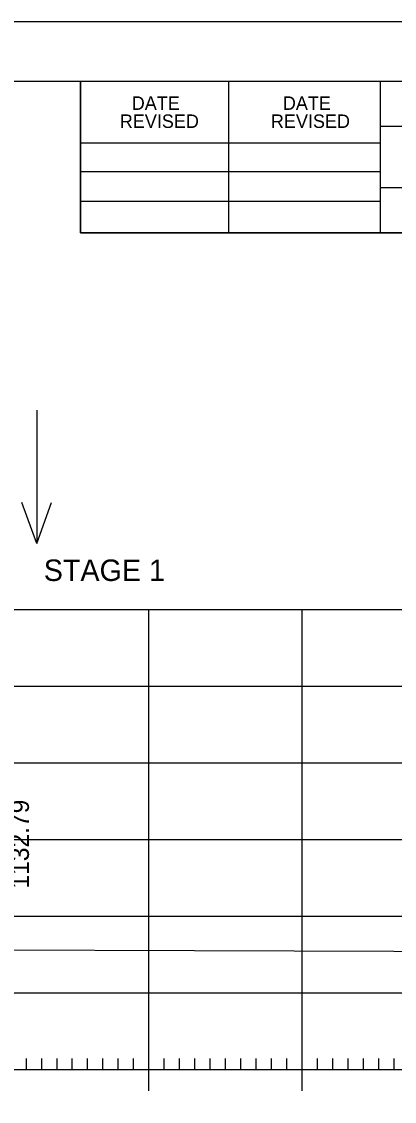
# Model space of a CAD drawing. Extents: x 1322838 to 1324533, y 339903 to 351025.
# Drawn here: x 1323795.4 to 1323819.7, y 342179.4 to 342249.8 of the extents above; entities that cross this region are included whole.
import ezdxf

# ---------------------------------------------------------------- set-up
doc = ezdxf.new("R2010")
doc.units = 0
for name, color, linetype in [('R_Axis', 7, 'Continuous'), ('R_Axis Annot', 7, 'Continuous'), ('R_Border', 7, 'Continuous'), ('R_Exist Surface', 7, 'Continuous'), ('R_Fin Surface Annot', 7, 'Continuous'), ('R_Grid', 7, 'Continuous'), ('R_No Plot', 7, 'Continuous'), ('R_Water Annot', 7, 'Continuous')]:
    doc.layers.add(name, color=color, linetype=linetype)

msp = doc.modelspace()

# ---------------------------------------------------------------- linework, layer by layer
at = {"layer": 'R_Axis'}
for p, q in [((1323803.715, 342180.082), (1323803.715, 342182.882)), ((1323813.715, 342180.082), (1323813.715, 342182.882)), ((1323795.715, 342181.482), (1323795.715, 342182.182)), ((1323796.715, 342181.482), (1323796.715, 342182.182)), ((1323797.715, 342181.482), (1323797.715, 342182.182)), ((1323798.715, 342181.482), (1323798.715, 342182.182)), ((1323799.715, 342181.482), (1323799.715, 342182.182)), ((1323800.715, 342181.482), (1323800.715, 342182.182)), ((1323801.715, 342181.482), (1323801.715, 342182.182)), ((1323802.715, 342181.482), (1323802.715, 342182.182)), ((1323804.715, 342181.482), (1323804.715, 342182.182)), ((1323805.715, 342181.482), (1323805.715, 342182.182)), ((1323806.715, 342181.482), (1323806.715, 342182.182)), ((1323807.715, 342181.482), (1323807.715, 342182.182)), ((1323808.715, 342181.482), (1323808.715, 342182.182)), ((1323809.715, 342181.482), (1323809.715, 342182.182)), ((1323810.715, 342181.482), (1323810.715, 342182.182)), ((1323811.715, 342181.482), (1323811.715, 342182.182)), ((1323812.715, 342181.482), (1323812.715, 342182.182)), ((1323814.715, 342181.482), (1323814.715, 342182.182)), ((1323815.715, 342181.482), (1323815.715, 342182.182)), ((1323816.715, 342181.482), (1323816.715, 342182.182)), ((1323817.715, 342181.482), (1323817.715, 342182.182)), ((1323818.715, 342181.482), (1323818.715, 342182.182)), ((1323819.715, 342181.482), (1323819.715, 342182.182)), ((1323563.715, 342181.482), (1323843.715, 342181.482))]:
    msp.add_line(p, q, dxfattribs=at)
at = {"layer": 'R_Border'}
for p, q in [((1323545.715, 342245.942), (1323861.895, 342245.942)), ((1323799.255, 342236.062), (1323799.255, 342245.942)), ((1323808.935, 342236.062), (1323808.935, 342245.942)), ((1323818.795, 342245.942), (1323818.795, 342236.062)), ((1323861.895, 342243.002), (1323818.795, 342243.002)), ((1323799.255, 342241.922), (1323818.795, 342241.922)), ((1323799.255, 342240.062), (1323818.795, 342240.062)), ((1323861.895, 342239.002), (1323818.795, 342239.002)), ((1323799.255, 342238.122), (1323818.795, 342238.122)), ((1323861.895, 342236.062), (1323799.255, 342236.062))]:
    msp.add_line(p, q, dxfattribs=at)
at = {"layer": 'R_Exist Surface'}
msp.add_lwpolyline([(1323780.633, 342189.331), (1323819.688, 342189.188), (1323843.715, 342189.173)], dxfattribs=at)
at = {"layer": 'R_Grid'}
for p, q in [((1323563.715, 342211.482), (1323843.715, 342211.482)), ((1323803.715, 342181.482), (1323803.715, 342211.482)), ((1323813.715, 342181.482), (1323813.715, 342211.482)), ((1323563.715, 342206.482), (1323843.715, 342206.482)), ((1323563.715, 342201.482), (1323843.715, 342201.482)), ((1323563.715, 342196.482), (1323843.715, 342196.482)), ((1323563.715, 342191.482), (1323843.715, 342191.482)), ((1323563.715, 342186.482), (1323843.715, 342186.482)), ((1323563.715, 342181.482), (1323843.715, 342181.482))]:
    msp.add_line(p, q, dxfattribs=at)
at = {"layer": 'R_No Plot'}
msp.add_line((1323533.315, 342249.837), (1323866.648, 342249.837), dxfattribs=at)
for points in [[(1323533.308, 342249.837), (1323866.648, 342249.837), (1323866.648, 342036.499), (1323533.308, 342036.499)], [(1323779.635, 342245.942), (1323799.255, 342245.942), (1323799.255, 342236.062), (1323815.368, 342236.062), (1323838.567, 342236.062), (1323838.567, 342203.392), (1323861.775, 342203.392), (1323861.895, 342040.482), (1323545.715, 342040.482), (1323545.715, 342245.942)]]:
    msp.add_lwpolyline(points, close=True, dxfattribs=at)
at = {"layer": 'R_Water Annot'}
for p, q in [((1323796.395, 342224.49), (1323796.395, 342215.8)), ((1323796.395, 342215.8), (1323795.427, 342218.46)), ((1323796.395, 342215.8), (1323797.363, 342218.46))]:
    msp.add_line(p, q, dxfattribs=at)

# ---------------------------------------------------------------- texts
at = {"layer": 'R_Axis Annot'}
msp.add_text('STAGE 1', height=1.4, dxfattribs=at).set_placement((1323796.852, 342213.344))
at = {"layer": 'R_Border'}
for s, p in [('DATE', (1323802.593, 342244.079)), ('DATE', (1323812.453, 342244.079)), ('REVISED', (1323801.813, 342242.899)), ('REVISED', (1323811.673, 342242.899))]:
    msp.add_text(s, height=0.8792, rotation=360, dxfattribs=at).set_placement(p)
at = {"layer": 'R_Fin Surface Annot'}
msp.add_text('1132.79', height=1.2, rotation=90, dxfattribs=at).set_placement((1323795.884, 342193.277))

doc.saveas('drawing.dxf')
